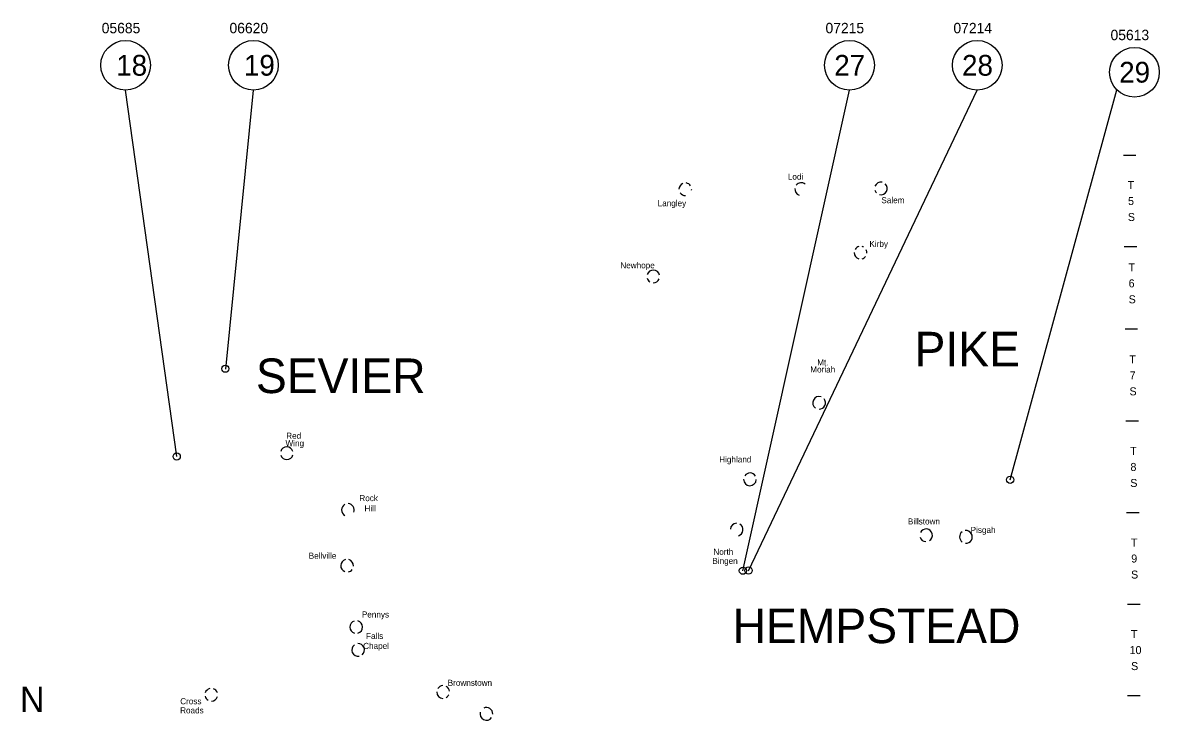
# Model space of a CAD drawing. Extents: x 3046 to 131673, y -8885 to 10756.
# Drawn here: x 72360 to 85487, y 130 to 8186 of the extents above; entities that cross this region are included whole.
import ezdxf

# ---------------------------------------------------------------- set-up
doc = ezdxf.new("R2010")
doc.units = 0
for name, color, linetype in [('2', 7, 'Continuous'), ('Default', 7, 'Continuous'), ('Level 24', 7, 'Continuous'), ('R_Annotation', 7, 'Continuous'), ('R_No Plot', 7, 'Continuous')]:
    doc.layers.add(name, color=color, linetype=linetype)

msp = doc.modelspace()

# ---------------------------------------------------------------- linework, layer by layer
at = {"layer": 'Default'}
for p, q in [((85218, 6653), (85072, 6653)), ((85228, 5599), (85081, 5599)), ((85228, 5599), (85081, 5599)), ((85237, 4648), (85091, 4648)), ((85237, 4648), (85091, 4648)), ((85247, 3585), (85100, 3585)), ((85247, 3585), (85100, 3585)), ((85256, 2527), (85110, 2527)), ((85265, 1469), (85119, 1469)), ((85265, 412), (85119, 412))]:
    msp.add_line(p, q, dxfattribs=at)
at = {"layer": 'Level 24'}
for centre, start, end in [((80013, 6263), 114.0729, 180.165), ((80013, 6263), 33.1167, 81.5609), ((81351, 6265), 51.8748, 142.6506), ((82272, 6273), 80.0594, 160.6556), ((82272, 6273), 257.7843, 47.0601), ((80013, 6263), 213.1469, 271.8342), ((80013, 6263), 351.6482, 357.0801), ((81351, 6265), 173.5957, 252.1213), ((82272, 6273), 194.5965, 225.4122), ((82037, 5531), 180, 253.9741), ((82037, 5531), 105.5546, 148.7363), ((82037, 5531), 63.1166, 74.1343), ((82037, 5531), 354.114, 25.0829), ((82037, 5531), 285.6194, 321.6135), ((79642, 5256), 11.6503, 162.8545), ((79642, 5256), 195.1541, 236.9519), ((79642, 5256), 270, 339.1714), ((81558, 3797), 72.4891, 236.2289), ((81558, 3797), 269.1186, 39.6185), ((75410, 3214), 17.3935, 163.8836), ((75410, 3214), 197.0319, 345.4455), ((80759, 2913), 179.0151, 357.5397), ((80759, 2913), 30.1714, 146.0724), ((76115, 2560), 338.0138, 86.0555), ((76115, 2560), 118.6763, 241.9462), ((80606, 2332), 90.6987, 175.0608), ((80606, 2332), 287.7447, 59.0362), ((82793, 2267), 198.0813, 268.0194), ((82793, 2267), 301.9162, 153.8945), ((83254, 2248), 128.0273, 234.5301), ((83254, 2248), 266.5318, 96.4044), ((76106, 1915), 105.3567, 248.6499), ((76106, 1915), 357.4738, 74.779), ((76106, 1915), 282.5441, 324.0512), ((76212, 1207), 107.64, 252.74), ((76212, 1207), 285.6439, 76.2472), ((76234, 942), 126.3035, 278.9776), ((76234, 942), 311.0322, 93.6502), ((77215, 457), 92.7713, 147.9068), ((74538, 426), 193.7121, 239.1239), ((74538, 426), 103.5879, 161.9823), ((74538, 426), 270.9259, 341.9489), ((74538, 426), 15.6078, 71.1261), ((77215, 457), 179.301, 268.4414), ((77215, 457), 6.1546, 61.1398), ((77215, 457), 300.6019, 333.6343), ((77715, 204), 358.4574, 114.0794), ((77715, 204), 163.3161, 325.6828)]:
    msp.add_arc(centre, 73.3, start, end, dxfattribs=at)
at = {"layer": 'R_Annotation'}
for p, q in [((74138, 3177), (73548, 7408)), ((74704, 4187), (75024, 7408)), ((80678, 1858), (81909, 7408)), ((80744, 1857), (83385, 7408)), ((83765, 2908), (84997, 7412))]:
    msp.add_line(p, q, dxfattribs=at)
for centre, radius in [((73548, 7695), 287), ((75024, 7695), 287), ((81909, 7695), 287), ((83385, 7695), 287), ((85200, 7614), 287), ((74700, 4191), 41.7), ((74138, 3177), 41.7), ((83765, 2908), 41.7), ((80678, 1858), 41.7), ((80743, 1860), 41.7)]:
    msp.add_circle(centre, radius, dxfattribs=at)

# ---------------------------------------------------------------- texts
at = {"layer": '2'}
for s, height, p in [('T', 92.4, (85122, 6266)), ('5', 92.4, (85126, 6081)), ('S', 92.4, (85124, 5897)), ('T', 92.4, (85131, 5315)), ('6', 92.4, (85133, 5130)), ('S', 92.4, (85133, 4946)), ('PIKE', 399.6, (82660, 4217)), ('T', 92.4, (85141, 4253)), ('SEVIER', 399.6, (75053, 3909)), ('7', 92.4, (85145, 4068)), ('S', 92.4, (85143, 3883)), ('T', 92.4, (85150, 3195)), ('8', 92.4, (85154, 3010)), ('S', 92.4, (85152, 2825)), ('T', 92.4, (85159, 2137)), ('9', 92.4, (85163, 1952)), ('S', 92.4, (85161, 1767)), ('HEMPSTEAD', 399.6, (80558, 1021)), ('T', 92.4, (85159, 1080)), ('10', 92.4, (85144, 895)), ('S', 92.4, (85161, 710))]:
    msp.add_text(s, height=height, dxfattribs=at).set_placement(p)
at = {"layer": 'Level 24'}
for s, p in [('Lodi', (81197, 6374)), ('Salem', (82277, 6102)), ('Langley', (79693, 6067)), ('Kirby', (82139, 5597)), ('Newhope', (79262, 5350)), ('Moriah', (81456, 4147)), ('Mt.', (81536, 4228)), ('Red', (75403, 3381)), ('Wing', (75395, 3295)), ('Highland', (80404, 3108)), ('Rock', (76248, 2661)), ('Hill', (76307, 2542)), ('Billstown', (82583, 2392)), ('Pisgah', (83308, 2294)), ('North', (80337, 2041)), ('Bellville', (75663, 1996)), ('Bingen', (80325, 1936)), ('Pennys', (76277, 1317)), ('Falls', (76325, 1069)), ('Chapel', (76292, 954)), ('Brownstown', (77268, 528)), ('Cross', (74179, 315)), ('Roads', (74178, 210))]:
    msp.add_text(s, height=70.4, dxfattribs=at).set_placement(p)
at = {"layer": 'R_Annotation'}
for s, height, p in [('18', 239.8, (73440, 7575)), ('19', 239.8, (74915, 7575)), ('27', 239.8, (81733, 7575)), ('28', 239.8, (83209, 7575)), ('29', 239.8, (85024, 7495)), ('N', 293, (72328, 225))]:
    msp.add_text(s, height=height, dxfattribs=at).set_placement(p)
at = {"layer": 'R_No Plot'}
for s, p in [('05685', (73272, 8065)), ('06620', (74748, 8065)), ('07215', (81632, 8065)), ('07214', (83109, 8065)), ('05613', (84924, 7985))]:
    msp.add_text(s, height=119.9, dxfattribs=at).set_placement(p)

doc.saveas('drawing.dxf')
